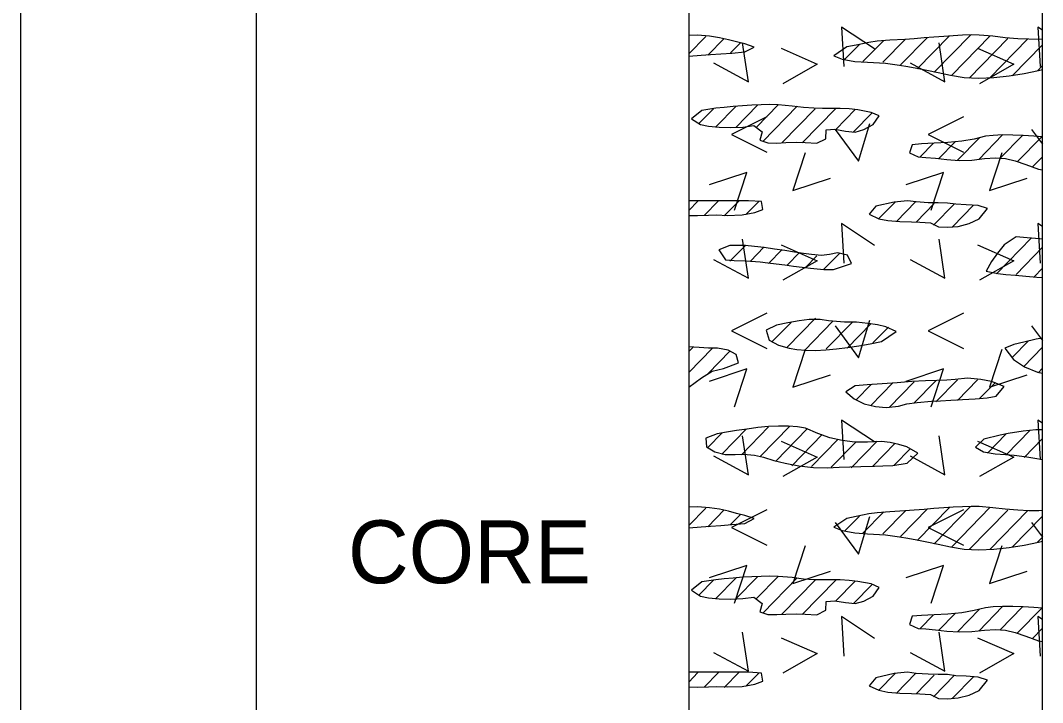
# Model space of a CAD drawing. Extents: x 0 to 0.83, y -0.65 to 1.27.
# Drawn here: x 0.725 to 0.8333, y -0.1595 to -0.0872 of the extents above; entities that cross this region are included whole.
import ezdxf

# ---------------------------------------------------------------- set-up
doc = ezdxf.new("R2010")
doc.units = 0

msp = doc.modelspace()

# ---------------------------------------------------------------- linework, layer by layer
for points in [[(0.725, 1.22083), (0.725, -0.64575)], [(0.75, 1.22083), (0.75, -0.64575)], [(0.75, 1.22083), (0.75, -0.64575)], [(0.79583, 1.22083), (0.79583, -0.64575)], [(0.725, 1.20833), (0.725, -0.64575)], [(0.83333, -0.64575), (0.83333, 1.13365)], [(0.81551, -0.09017), (0.81201, -0.08786), (0.81226, -0.09205)], [(0.82004, -0.09229), (0.82346, -0.08878)], [(0.82569, -0.0887), (0.82184, -0.09265)], [(0.82775, -0.08881), (0.8237, -0.09295)], [(0.83333, -0.08818), (0.83284, -0.08786), (0.83309, -0.09205)], [(0.79765, -0.08885), (0.79583, -0.09071)], [(0.7996, -0.08906), (0.79786, -0.09084)], [(0.79847, -0.09166), (0.80215, -0.09366), (0.80153, -0.08953)], [(0.8013, -0.08954), (0.80027, -0.09059)], [(0.81392, -0.0897), (0.81235, -0.09131)], [(0.8143, -0.09152), (0.8165, -0.08927)], [(0.8164, -0.09159), (0.81879, -0.08914)], [(0.81829, -0.09187), (0.82114, -0.08895)], [(0.8193, -0.09166), (0.82299, -0.09366), (0.82236, -0.08953)], [(0.82964, -0.08908), (0.82557, -0.09326)], [(0.83173, -0.08915), (0.82774, -0.09324)], [(0.83333, -0.08973), (0.83012, -0.09302)], [(0.80562, -0.09011), (0.80946, -0.09179), (0.80581, -0.09386)], [(0.82645, -0.09011), (0.83029, -0.09179), (0.82664, -0.09386)], [(0.83281, -0.09248), (0.83333, -0.09194)], [(0.79871, -0.09845), (0.80085, -0.09625)], [(0.80083, -0.09849), (0.80311, -0.09615)], [(0.80534, -0.09607), (0.80299, -0.09849)], [(0.80367, -0.1), (0.80732, -0.09626)], [(0.79844, -0.09651), (0.79691, -0.09808)], [(0.80412, -0.09737), (0.80038, -0.09924), (0.80412, -0.10112)], [(0.80571, -0.10012), (0.80924, -0.09651)], [(0.81142, -0.09649), (0.80785, -0.10014)], [(0.81141, -0.09871), (0.81348, -0.09659)], [(0.81528, -0.09695), (0.81331, -0.09897)], [(0.82496, -0.09737), (0.82121, -0.09924), (0.82496, -0.10112)], [(0.81134, -0.09871), (0.81384, -0.10208), (0.81503, -0.09808)], [(0.82433, -0.10198), (0.82666, -0.09959)], [(0.82909, -0.0993), (0.82656, -0.1019)], [(0.82885, -0.10177), (0.83122, -0.09934)], [(0.83325, -0.09948), (0.83065, -0.10214)], [(0.83217, -0.09871), (0.83333, -0.10027)], [(0.82035, -0.10163), (0.82176, -0.10018)], [(0.82233, -0.10181), (0.82408, -0.10002)], [(0.80818, -0.1012), (0.80687, -0.1052), (0.81087, -0.10389)], [(0.82901, -0.1012), (0.8277, -0.1052), (0.8317, -0.10389)], [(0.83333, -0.1016), (0.83227, -0.10269)], [(0.80069, -0.10728), (0.802, -0.10328), (0.798, -0.10459)], [(0.82152, -0.10728), (0.82284, -0.10328), (0.81884, -0.10459)], [(0.79583, -0.1073), (0.79681, -0.1063)], [(0.79898, -0.10628), (0.79747, -0.10783)], [(0.80116, -0.10627), (0.79959, -0.10787)], [(0.80328, -0.10631), (0.80188, -0.10774)], [(0.8177, -0.10641), (0.81596, -0.10819)], [(0.81988, -0.10639), (0.81785, -0.10847)], [(0.82185, -0.10658), (0.81997, -0.10851)], [(0.824, -0.10659), (0.82178, -0.10887)], [(0.82601, -0.10675), (0.82378, -0.10903)], [(0.81551, -0.11101), (0.81201, -0.10869), (0.81226, -0.11288)], [(0.83333, -0.10902), (0.83284, -0.10869), (0.83309, -0.11288)], [(0.79847, -0.11249), (0.80215, -0.11449), (0.80153, -0.11036)], [(0.8193, -0.11249), (0.82299, -0.11449), (0.82236, -0.11036)], [(0.83217, -0.11019), (0.82844, -0.11401)], [(0.80188, -0.11097), (0.8002, -0.11269)], [(0.8038, -0.11121), (0.80237, -0.11267)], [(0.80575, -0.11143), (0.80429, -0.11292)], [(0.80562, -0.11094), (0.80946, -0.11263), (0.80581, -0.11469)], [(0.82645, -0.11094), (0.83029, -0.11263), (0.82664, -0.11469)], [(0.83333, -0.11121), (0.83052, -0.11409)], [(0.80758, -0.11176), (0.80627, -0.11311)], [(0.80941, -0.1121), (0.80816, -0.11338)], [(0.81188, -0.11178), (0.81016, -0.11354)], [(0.83333, -0.11343), (0.83245, -0.11433)], [(0.80412, -0.1182), (0.80038, -0.12008), (0.80412, -0.12195)], [(0.80626, -0.12181), (0.80928, -0.11871)], [(0.80809, -0.12214), (0.81111, -0.11905)], [(0.81041, -0.12198), (0.81318, -0.11915)], [(0.81134, -0.11954), (0.81384, -0.12292), (0.81503, -0.11892)], [(0.82496, -0.1182), (0.82121, -0.12008), (0.82496, -0.12195)], [(0.80465, -0.12124), (0.80667, -0.11917)], [(0.81264, -0.1219), (0.81518, -0.1193)], [(0.81536, -0.12133), (0.81699, -0.11967)], [(0.83217, -0.11954), (0.83333, -0.1211)], [(0.8301, -0.12291), (0.83184, -0.12112)], [(0.7963, -0.12179), (0.79583, -0.12227)], [(0.79834, -0.12192), (0.79583, -0.12449)], [(0.79786, -0.12462), (0.80023, -0.12219)], [(0.80818, -0.12203), (0.80687, -0.12603), (0.81087, -0.12472)], [(0.82901, -0.12203), (0.8277, -0.12603), (0.8317, -0.12472)], [(0.83131, -0.12388), (0.83333, -0.12181)], [(0.80069, -0.12811), (0.802, -0.12411), (0.798, -0.12543)], [(0.82152, -0.12811), (0.82284, -0.12411), (0.81884, -0.12543)], [(0.83285, -0.12451), (0.83333, -0.12402)], [(0.81514, -0.12798), (0.81748, -0.12559)], [(0.81709, -0.1282), (0.81974, -0.12549)], [(0.8197, -0.12775), (0.82203, -0.12535)], [(0.82202, -0.12758), (0.8243, -0.12525)], [(0.82431, -0.12745), (0.82644, -0.12526)], [(0.82663, -0.12728), (0.82834, -0.12553)], [(0.81519, -0.12572), (0.81354, -0.12742)], [(0.81551, -0.13184), (0.81201, -0.12953), (0.81226, -0.13371)], [(0.83333, -0.12985), (0.83284, -0.12953), (0.83309, -0.13371)], [(0.79938, -0.13087), (0.79786, -0.13242)], [(0.79933, -0.13313), (0.80195, -0.13044)], [(0.80142, -0.1332), (0.8043, -0.13025)], [(0.80653, -0.13017), (0.8034, -0.13339)], [(0.80506, -0.13389), (0.8084, -0.13047)], [(0.80997, -0.13107), (0.80675, -0.13438)], [(0.82751, -0.13302), (0.82945, -0.13103)], [(0.83203, -0.13061), (0.82949, -0.13321)], [(0.79847, -0.13332), (0.80215, -0.13532), (0.80153, -0.1312)], [(0.80562, -0.13178), (0.80946, -0.13346), (0.80581, -0.13552)], [(0.81164, -0.13158), (0.80884, -0.13444)], [(0.81353, -0.13186), (0.81094, -0.13451)], [(0.81303, -0.13458), (0.81579, -0.13175)], [(0.81534, -0.13442), (0.81768, -0.13202)], [(0.8193, -0.13332), (0.82299, -0.13532), (0.82236, -0.1312)], [(0.82645, -0.13178), (0.83029, -0.13346), (0.82664, -0.13552)], [(0.83138, -0.13348), (0.83333, -0.13148)], [(0.8176, -0.13432), (0.81934, -0.13253)], [(0.83333, -0.1337), (0.83333, -0.13369)], [(0.79765, -0.13885), (0.79583, -0.14071)], [(0.7996, -0.13906), (0.79786, -0.14084)], [(0.8013, -0.13954), (0.80027, -0.14059)], [(0.80412, -0.13903), (0.80038, -0.14091), (0.80412, -0.14278)], [(0.81392, -0.1397), (0.81235, -0.14131)], [(0.8143, -0.14152), (0.8165, -0.13927)], [(0.8164, -0.14159), (0.81879, -0.13914)], [(0.81829, -0.14187), (0.82114, -0.13894)], [(0.82004, -0.14229), (0.82346, -0.13878)], [(0.82496, -0.13903), (0.82121, -0.14091), (0.82496, -0.14278)], [(0.82569, -0.1387), (0.82184, -0.14265)], [(0.82775, -0.13881), (0.8237, -0.14295)], [(0.82964, -0.13908), (0.82557, -0.14326)], [(0.83173, -0.13915), (0.82774, -0.14324)], [(0.83333, -0.13973), (0.83012, -0.14302)], [(0.81134, -0.14038), (0.81384, -0.14375), (0.81503, -0.13975)], [(0.83217, -0.14038), (0.83333, -0.14194)], [(0.80818, -0.14287), (0.80687, -0.14687), (0.81087, -0.14555)], [(0.82901, -0.14287), (0.8277, -0.14687), (0.8317, -0.14555)], [(0.83281, -0.14247), (0.83333, -0.14194)], [(0.80069, -0.14895), (0.802, -0.14495), (0.798, -0.14626)], [(0.82152, -0.14895), (0.82284, -0.14495), (0.81884, -0.14626)], [(0.80083, -0.14849), (0.80311, -0.14615)], [(0.80534, -0.14607), (0.80299, -0.14849)], [(0.79844, -0.14651), (0.79691, -0.14808)], [(0.79871, -0.14845), (0.80085, -0.14625)], [(0.80367, -0.15), (0.80732, -0.14626)], [(0.80571, -0.15012), (0.80924, -0.14651)], [(0.81142, -0.14649), (0.80785, -0.15014)], [(0.81141, -0.14871), (0.81348, -0.14659)], [(0.81528, -0.14695), (0.81331, -0.14897)], [(0.82909, -0.1493), (0.82656, -0.1519)], [(0.82885, -0.15177), (0.83122, -0.14934)], [(0.83325, -0.14948), (0.83065, -0.15213)], [(0.81551, -0.15267), (0.81201, -0.15036), (0.81226, -0.15455)], [(0.82035, -0.15163), (0.82176, -0.15018)], [(0.82233, -0.15181), (0.82408, -0.15002)], [(0.82433, -0.15198), (0.82666, -0.14959)], [(0.83333, -0.15068), (0.83284, -0.15036), (0.83309, -0.15455)], [(0.83333, -0.1516), (0.83227, -0.15269)], [(0.79847, -0.15416), (0.80215, -0.15616), (0.80153, -0.15203)], [(0.80562, -0.15261), (0.80946, -0.15429), (0.80581, -0.15636)], [(0.8193, -0.15416), (0.82299, -0.15616), (0.82236, -0.15203)], [(0.82645, -0.15261), (0.83029, -0.15429), (0.82664, -0.15636)], [(0.79583, -0.1573), (0.79681, -0.1563)], [(0.79898, -0.15628), (0.79747, -0.15783)], [(0.80116, -0.15627), (0.79959, -0.15787)], [(0.80328, -0.15631), (0.80188, -0.15774)], [(0.8177, -0.15641), (0.81596, -0.15819)], [(0.81988, -0.15639), (0.81785, -0.15847)], [(0.82185, -0.15658), (0.81997, -0.15851)], [(0.824, -0.15659), (0.82178, -0.15887)], [(0.82601, -0.15675), (0.82378, -0.15903)]]:
    msp.add_lwpolyline(points)
for points in [[(0.79583, -0.09096), (0.79715, -0.09085), (0.79814, -0.09078), (0.79922, -0.0907), (0.80039, -0.09061), (0.80179, -0.09049), (0.80275, -0.08998), (0.80179, -0.08964), (0.80091, -0.08942), (0.80003, -0.0892), (0.79909, -0.08899), (0.79803, -0.08883), (0.79677, -0.08873), (0.79583, -0.08875)], [(0.82816, -0.09321), (0.82978, -0.09304), (0.83137, -0.09279), (0.8329, -0.09247), (0.83333, -0.09237), (0.83333, -0.08913), (0.83295, -0.08916), (0.83188, -0.08914), (0.83071, -0.08909), (0.82938, -0.08899), (0.82807, -0.08882), (0.82662, -0.0887), (0.82576, -0.08869), (0.82484, -0.08872), (0.82387, -0.08877), (0.82286, -0.08884), (0.82182, -0.08892), (0.82077, -0.089), (0.81973, -0.08909), (0.81872, -0.08916), (0.81715, -0.08926), (0.81579, -0.08935), (0.81491, -0.08948), (0.81357, -0.08976), (0.8126, -0.08997), (0.81121, -0.09089), (0.8121, -0.09125), (0.81345, -0.0915), (0.81479, -0.09159), (0.81668, -0.09169), (0.81818, -0.09189), (0.81905, -0.09204), (0.82, -0.09222), (0.82107, -0.09243), (0.82225, -0.09268), (0.82357, -0.09297), (0.82501, -0.0932), (0.82656, -0.09327)], [(0.79708, -0.09819), (0.79794, -0.09837), (0.79904, -0.09848), (0.80028, -0.09851), (0.80156, -0.09846), (0.80274, -0.0983), (0.80361, -0.09897), (0.80338, -0.09986), (0.80422, -0.10013), (0.80517, -0.10015), (0.80613, -0.1001), (0.8072, -0.10007), (0.80818, -0.1001), (0.80939, -0.10017), (0.81037, -0.0997), (0.81038, -0.09876), (0.8113, -0.09869), (0.81244, -0.09888), (0.81346, -0.09899), (0.81438, -0.09873), (0.81539, -0.09819), (0.81601, -0.09728), (0.81517, -0.0969), (0.81374, -0.09663), (0.81285, -0.09654), (0.81187, -0.09648), (0.81, -0.09648), (0.8091, -0.09646), (0.808, -0.09638), (0.80678, -0.09623), (0.8053, -0.0961), (0.80443, -0.09608), (0.80349, -0.0961), (0.80251, -0.09614), (0.80152, -0.0962), (0.80054, -0.09628), (0.79959, -0.09637), (0.7987, -0.09647), (0.79722, -0.09669), (0.79614, -0.09757)], [(0.83241, -0.09941), (0.83129, -0.09934), (0.83017, -0.09931), (0.8291, -0.0993), (0.82811, -0.09934), (0.82728, -0.09943), (0.82608, -0.09973), (0.82476, -0.09996), (0.8233, -0.10009), (0.82183, -0.10018), (0.82051, -0.10024), (0.81951, -0.10033), (0.81922, -0.1012), (0.82013, -0.10162), (0.82097, -0.10167), (0.822, -0.10177), (0.82318, -0.1019), (0.82448, -0.10199), (0.82584, -0.10196), (0.82719, -0.1018), (0.82836, -0.10173), (0.8294, -0.10181), (0.83043, -0.10204), (0.83156, -0.10244), (0.83291, -0.10293), (0.83333, -0.103), (0.83333, -0.09948)], [(0.79583, -0.10782), (0.79676, -0.10783), (0.79792, -0.10781), (0.79882, -0.10777), (0.79992, -0.10782), (0.80151, -0.10777), (0.80282, -0.10752), (0.80367, -0.1072), (0.80354, -0.10636), (0.80216, -0.10627), (0.79583, -0.10627)], [(0.81822, -0.10847), (0.81944, -0.10852), (0.82033, -0.10856), (0.82145, -0.10863), (0.82229, -0.10905), (0.82324, -0.10909), (0.82438, -0.10899), (0.82555, -0.1087), (0.82662, -0.10819), (0.82749, -0.1071), (0.82651, -0.10679), (0.82524, -0.10669), (0.82413, -0.10663), (0.82324, -0.10652), (0.82226, -0.1065), (0.82121, -0.10648), (0.81995, -0.10639), (0.81902, -0.10627), (0.81761, -0.10641), (0.81566, -0.10685), (0.81496, -0.10769), (0.81598, -0.10818), (0.81695, -0.10836)], [(0.83305, -0.11032), (0.83171, -0.11021), (0.83054, -0.11011), (0.82925, -0.11093), (0.82857, -0.11184), (0.82792, -0.11273), (0.82735, -0.11375), (0.82858, -0.11398), (0.82945, -0.11408), (0.83045, -0.11418), (0.83155, -0.11427), (0.83272, -0.11437), (0.83333, -0.11442), (0.83333, -0.11033)], [(0.80066, -0.11262), (0.80188, -0.11263), (0.80339, -0.11276), (0.80423, -0.11285), (0.8051, -0.11296), (0.806, -0.11308), (0.80692, -0.1132), (0.80784, -0.11332), (0.80875, -0.11343), (0.81014, -0.11357), (0.81119, -0.11356), (0.81222, -0.11322), (0.81308, -0.11293), (0.81267, -0.11203), (0.8116, -0.11178), (0.81075, -0.11198), (0.80989, -0.11206), (0.80885, -0.11198), (0.80799, -0.11187), (0.80703, -0.11173), (0.806, -0.11156), (0.80492, -0.1114), (0.80384, -0.11124), (0.8028, -0.11111), (0.80182, -0.11101), (0.8002, -0.11101), (0.79901, -0.11148), (0.79974, -0.11252)], [(0.81233, -0.11913), (0.81063, -0.11901), (0.80977, -0.11888), (0.8086, -0.11887), (0.80755, -0.11901), (0.80632, -0.11921), (0.80513, -0.11946), (0.80403, -0.11998), (0.80436, -0.12104), (0.80536, -0.1216), (0.80647, -0.1219), (0.8073, -0.12205), (0.80824, -0.12213), (0.80926, -0.12214), (0.81035, -0.12209), (0.81149, -0.12198), (0.81267, -0.12184), (0.81386, -0.12165), (0.81506, -0.12144), (0.81625, -0.12121), (0.81783, -0.12013), (0.81673, -0.11963), (0.81585, -0.11942), (0.8148, -0.11927), (0.81361, -0.11916)], [(0.83265, -0.12094), (0.83136, -0.12125), (0.83028, -0.12152), (0.82934, -0.12192), (0.83026, -0.12312), (0.83142, -0.12388), (0.83279, -0.12446), (0.83333, -0.12456), (0.83333, -0.12085)], [(0.79583, -0.12604), (0.79719, -0.12505), (0.79831, -0.12435), (0.79951, -0.12407), (0.80111, -0.12347), (0.80086, -0.12259), (0.80002, -0.12211), (0.79889, -0.12192), (0.79791, -0.12189), (0.79694, -0.12183), (0.79583, -0.12175)], [(0.82537, -0.12509), (0.82408, -0.12524), (0.82319, -0.1253), (0.82214, -0.12532), (0.82091, -0.12536), (0.81947, -0.12545), (0.81792, -0.12557), (0.81632, -0.12569), (0.81475, -0.12579), (0.81348, -0.12589), (0.81247, -0.12653), (0.81337, -0.12729), (0.81444, -0.12779), (0.81561, -0.12808), (0.81675, -0.12819), (0.81807, -0.12807), (0.81896, -0.1278), (0.82003, -0.12765), (0.82157, -0.12753), (0.82253, -0.12747), (0.82362, -0.12742), (0.82483, -0.12735), (0.82618, -0.12729), (0.82745, -0.12718), (0.82842, -0.127), (0.82927, -0.12595), (0.82791, -0.12543), (0.82679, -0.12523)], [(0.79885, -0.131), (0.79763, -0.13146), (0.79773, -0.13236), (0.79859, -0.13288), (0.7997, -0.13318), (0.80074, -0.13317), (0.80165, -0.13315), (0.80281, -0.13324), (0.80377, -0.13345), (0.80486, -0.1338), (0.80606, -0.13409), (0.80751, -0.13437), (0.80905, -0.13455), (0.81052, -0.13458), (0.81177, -0.13452), (0.81289, -0.13448), (0.81408, -0.13445), (0.81553, -0.13441), (0.81642, -0.13438), (0.81745, -0.13435), (0.81897, -0.13408), (0.82011, -0.13304), (0.81896, -0.13237), (0.8181, -0.13211), (0.81717, -0.13191), (0.81626, -0.1318), (0.81479, -0.13186), (0.81343, -0.13186), (0.8121, -0.13171), (0.8108, -0.13141), (0.80953, -0.13095), (0.8082, -0.1304), (0.80736, -0.13024), (0.8064, -0.13016), (0.80536, -0.13016), (0.80427, -0.13022), (0.80314, -0.13033), (0.80201, -0.13048), (0.8009, -0.13064), (0.79984, -0.13082)], [(0.83263, -0.13056), (0.83126, -0.13069), (0.82969, -0.13096), (0.82883, -0.13113), (0.82712, -0.13154), (0.82623, -0.13241), (0.82708, -0.1329), (0.82831, -0.13309), (0.82941, -0.13316), (0.83033, -0.13324), (0.83165, -0.13343), (0.83253, -0.13357), (0.83333, -0.13371), (0.83333, -0.13056)], [(0.79583, -0.14096), (0.79715, -0.14085), (0.79814, -0.14078), (0.79922, -0.1407), (0.80039, -0.14061), (0.80179, -0.14049), (0.80275, -0.13998), (0.80179, -0.13964), (0.80091, -0.13942), (0.80003, -0.1392), (0.79909, -0.13899), (0.79803, -0.13883), (0.79677, -0.13873), (0.79583, -0.13875)], [(0.82816, -0.14321), (0.82978, -0.14304), (0.83137, -0.14279), (0.8329, -0.14247), (0.83333, -0.14237), (0.83333, -0.13913), (0.83295, -0.13916), (0.83188, -0.13914), (0.83071, -0.13909), (0.82938, -0.13899), (0.82807, -0.13882), (0.82662, -0.1387), (0.82576, -0.13869), (0.82484, -0.13872), (0.82387, -0.13877), (0.82286, -0.13884), (0.82182, -0.13892), (0.82077, -0.139), (0.81973, -0.13909), (0.81872, -0.13916), (0.81715, -0.13926), (0.81579, -0.13935), (0.81491, -0.13948), (0.81357, -0.13976), (0.8126, -0.13997), (0.81121, -0.14089), (0.8121, -0.14125), (0.81345, -0.1415), (0.81479, -0.14159), (0.81668, -0.14169), (0.81818, -0.14189), (0.81905, -0.14204), (0.82, -0.14222), (0.82107, -0.14243), (0.82225, -0.14268), (0.82357, -0.14297), (0.82501, -0.1432), (0.82656, -0.14327)], [(0.79708, -0.14819), (0.79794, -0.14837), (0.79904, -0.14848), (0.80028, -0.14851), (0.80156, -0.14846), (0.80274, -0.1483), (0.80361, -0.14897), (0.80338, -0.14986), (0.80422, -0.15013), (0.80517, -0.15015), (0.80613, -0.1501), (0.8072, -0.15007), (0.80818, -0.1501), (0.80939, -0.15017), (0.81037, -0.1497), (0.81038, -0.14876), (0.8113, -0.14869), (0.81244, -0.14888), (0.81346, -0.14899), (0.81438, -0.14873), (0.81539, -0.14819), (0.81601, -0.14728), (0.81517, -0.1469), (0.81374, -0.14663), (0.81285, -0.14654), (0.81187, -0.14648), (0.81, -0.14647), (0.8091, -0.14646), (0.808, -0.14638), (0.80678, -0.14623), (0.8053, -0.1461), (0.80443, -0.14608), (0.80349, -0.1461), (0.80251, -0.14614), (0.80152, -0.1462), (0.80054, -0.14628), (0.79959, -0.14637), (0.7987, -0.14647), (0.79722, -0.14669), (0.79614, -0.14757)], [(0.83241, -0.14941), (0.83129, -0.14934), (0.83017, -0.14931), (0.8291, -0.1493), (0.82811, -0.14934), (0.82728, -0.14943), (0.82608, -0.14973), (0.82476, -0.14996), (0.8233, -0.15009), (0.82183, -0.15018), (0.82051, -0.15024), (0.81951, -0.15033), (0.81922, -0.1512), (0.82013, -0.15162), (0.82097, -0.15167), (0.822, -0.15177), (0.82318, -0.1519), (0.82448, -0.15199), (0.82584, -0.15196), (0.82719, -0.1518), (0.82836, -0.15173), (0.8294, -0.15181), (0.83043, -0.15204), (0.83156, -0.15244), (0.83291, -0.15293), (0.83333, -0.153), (0.83333, -0.14948)], [(0.79583, -0.15782), (0.79676, -0.15783), (0.79792, -0.15781), (0.79882, -0.15777), (0.79992, -0.15782), (0.80151, -0.15777), (0.80282, -0.15752), (0.80367, -0.1572), (0.80354, -0.15636), (0.80216, -0.15627), (0.79583, -0.15627)], [(0.81822, -0.15847), (0.81944, -0.15852), (0.82033, -0.15856), (0.82145, -0.15863), (0.82229, -0.15905), (0.82324, -0.15909), (0.82438, -0.15899), (0.82555, -0.1587), (0.82662, -0.15819), (0.82749, -0.1571), (0.82651, -0.15679), (0.82524, -0.15669), (0.82413, -0.15663), (0.82324, -0.15652), (0.82226, -0.1565), (0.82121, -0.15648), (0.81995, -0.15639), (0.81902, -0.15627), (0.81761, -0.15641), (0.81566, -0.15685), (0.81496, -0.15769), (0.81598, -0.15818), (0.81695, -0.15836)]]:
    msp.add_lwpolyline(points, close=True)

# ---------------------------------------------------------------- texts
msp.add_text('CORE', height=0.006667).set_placement((0.75971, -0.14683))

doc.saveas('drawing.dxf')
